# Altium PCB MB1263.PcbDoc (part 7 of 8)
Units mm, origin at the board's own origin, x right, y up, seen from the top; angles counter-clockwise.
Board outline 86 x 120 mm, 6 copper layers (Top Layer, Signal Layer 1, Signal Layer 2, Signal Layer 3, Signal Layer 4, Bottom Layer), stack 1.556 mm thick; 392 components, 421 nets, 1978 pads, 1444 vias.
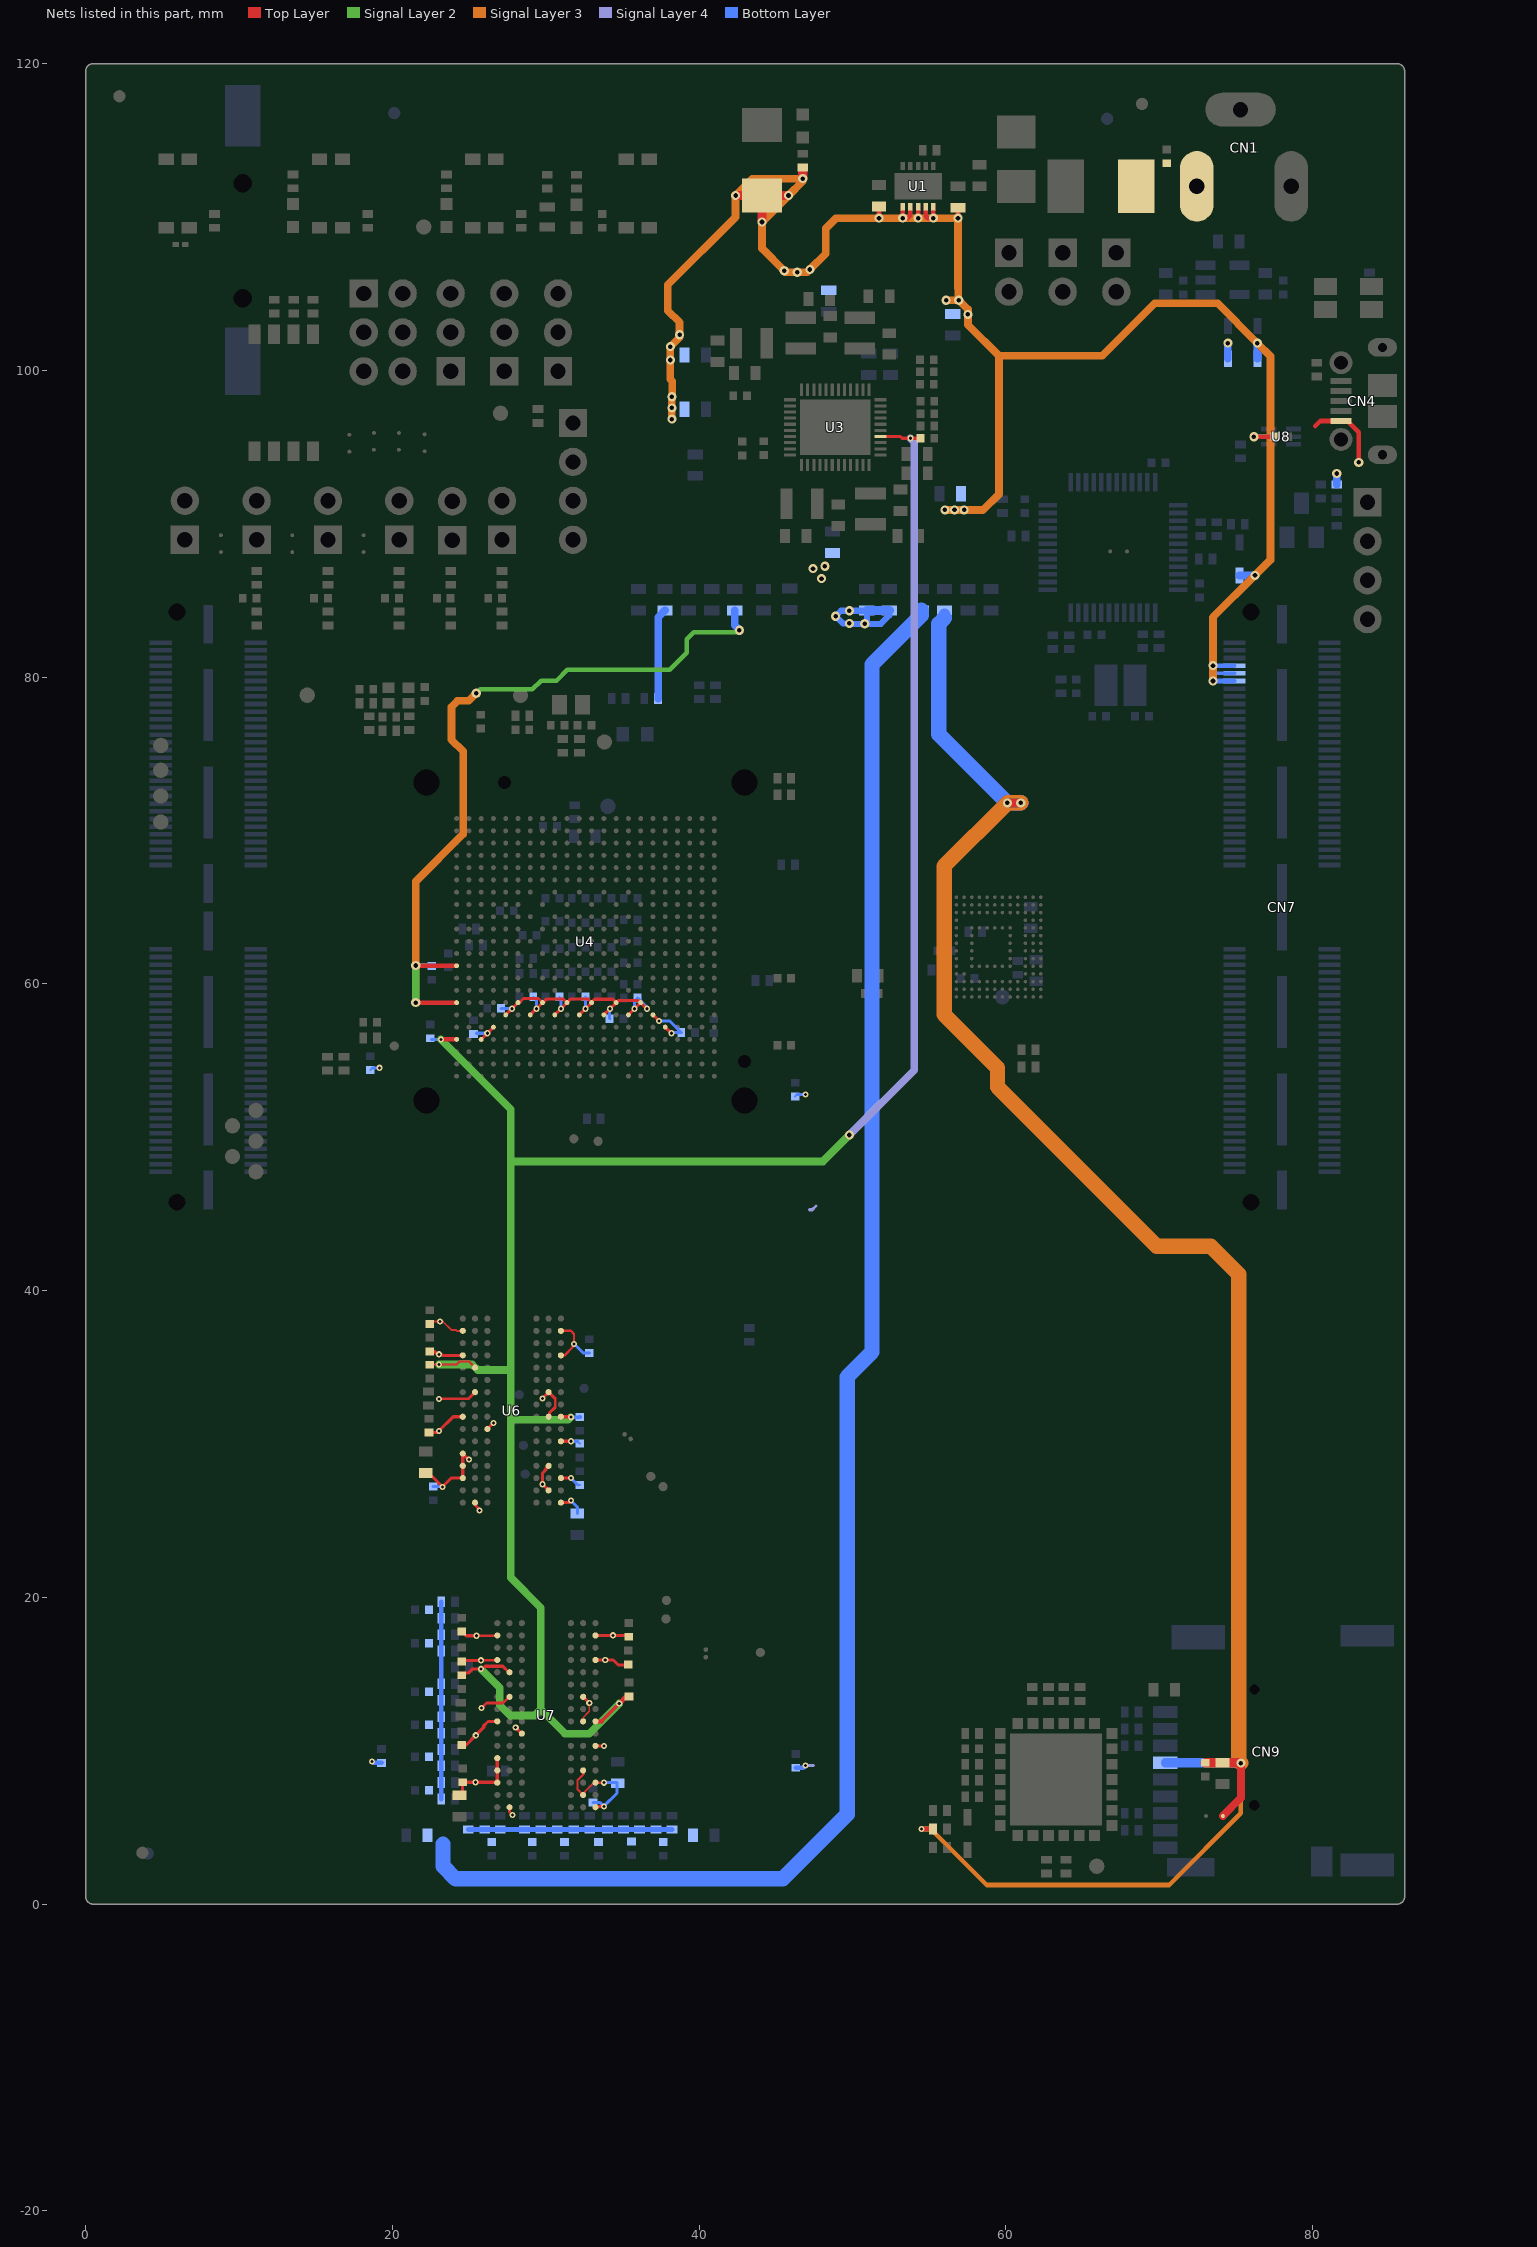
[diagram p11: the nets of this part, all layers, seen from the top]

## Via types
v1: diameter 0.4, hole 0.2, Top Layer to Bottom Layer, tented both sides, 771 vias
v2: diameter 0.6, hole 0.3, Top Layer to Bottom Layer, tented both sides, 670 vias
v3: diameter 0.4, hole 0.2, Top Layer to Bottom Layer, 3 vias

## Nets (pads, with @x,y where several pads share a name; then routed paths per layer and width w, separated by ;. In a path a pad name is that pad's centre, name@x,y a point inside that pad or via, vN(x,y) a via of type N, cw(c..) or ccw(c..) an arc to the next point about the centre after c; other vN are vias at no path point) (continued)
VDD_DDR: C44.1 C45.1 C47.1 C48.2 C49.1 C50.1 C51.1 C52.1 C59.2 C65.1 C66.1 C105.2 C106.2 C107.2 C108.2 C109.2 C110.2 C112.2 C114.2 C115.1 C116.1 C117.1 C119.1 C120.1 C121.1 C122.2 C127.1 C128.1 C130.2 C131.1 LNK2.2 R79.1 R80.2 U4.E18 U4.F17 U4.G16 U4.H17 U4.J16 U4.K17 U4.L16 U4.M17 U4.N16 U4.P17 U4.R16 U4.T17 U4.U16 U4.V17 U4.W18 U4.Y19 U6.A1 U6.A8 U6.B2 U6.C1 U6.C9 U6.D2 U6.D9 U6.E9 U6.F1 U6.G7 U6.H2 U6.H9 U6.K2 U6.K8 U6.N1 U6.N9 U6.R1 U6.R9 U7.A1 U7.A8 U7.B2 U7.C1 U7.C9 U7.D2 U7.D9 U7.E9 U7.F1 U7.G7 U7.H2 U7.H9 U7.K2 U7.K8 U7.N1 U7.N9 U7.R1 U7.R9 | length 100.6
  Top Layer w0.12: C44.1@22.43,37.82 22.6,37.99 v1(23.11,37.99) 23.291,37.99 23.841,37.44 24.139,37.44 24.199,37.38 U6.R9@24.59,37.38 U6.R9@24.64,37.38 ; U6.C1@30.979,27.825 U6.C1@31.004,27.8 ; U7.H2@32.44,11.92 32.44,12.17 32.84,12.57 v1(32.84,13.12) ; U7.A1@33.24,6.32 U7.A1@33.3,6.38 ; U4.G16@36.19,58.73 36.19,58.76 U4.G16@36.19,58.78
  Top Layer w0.15: v1(23.03,32.94) 23.045,32.955 24.965,32.955 ; v1(25.49,17.5) 25.5,17.51 U7.R9@26.8,17.51 ; v1(25.79,15.9) U7.N9@26.79,15.9 ; 30.615,32.405 30.615,32.955 ; U6.N1@30.99,35.78 31.22,35.78 31.76,36.32 31.76,36.45 v1(31.84,36.53) 31.84,37.18 31.64,37.38 U6.R1@30.99,37.38 ; U7.D2@32.44,8.72 32.44,8.45 32.285,8.295 32.065,8.075 32.065,7.495 U7.B2@32.44,7.12 32.44,7.23 33.13,7.92 U7.C1@33.24,7.92 v1(33.79,7.92)
  Top Layer w0.2: C48.2@22.18,28.11 22.37,28.11 v1(23.27,27.21) 23.84,27.78 U6.C9@24.59,27.78 U6.D9@24.59,28.58 U6.E9@24.59,29.38 v1(24.99,28.98) ; C47.1@22.39,30.75 22.93,30.75 v1(23.03,30.85) 23.96,31.78 U6.H9@24.59,31.78 ; C45.1@22.43,36.04 22.73,36.04 22.92,35.85 v1(23.04,35.85) 23.193,35.85 23.263,35.78 U6.N9@24.59,35.78 ; C59.2@24.38,7.1 24.58,7.3 24.58,7.95 v1(25.43,7.95) 26.81,7.95 U7.C9@26.84,7.92 U7.D9@26.84,8.72 U7.E9@26.84,9.52 ; C51.1@24.52,15.83 24.59,15.9 v1(25.79,15.9) ; C65.1@24.53,10.37 24.8,10.37 v1(25.44,11.01) 25.96,11.53 25.96,11.64 26.23,11.91 U7.H9@26.8,11.91 ; C49.1@24.53,17.77 24.8,17.5 v1(25.49,17.5) ; U6.E9@24.64,29.38 U6.E9@24.683,29.38 ; U6.H9@24.64,31.75 U6.H9@24.64,31.78 ; 24.965,32.955 U6.K8@25.39,33.38 U6.K8@25.44,33.38 ; U6.A8@25.39,26.18 25.39,26.02 25.69,25.72 25.68,25.71 v1(25.68,25.67) ; U4.Y19@25.79,56.38 v1(26.19,56.78) U4.W18@26.59,57.18 ; v1(25.8,12.78) 26.14,13.12 27.21,13.12 U7.K8@27.6,13.51 ; U6.G7@26.19,30.98 v1(26.59,31.38) ; U7.N9@26.79,15.9 U7.N9@26.8,15.91 ; U4.V17@27.39,57.98 v1(27.79,58.38) U4.U16@28.19,58.78 28.28,58.78 28.55,59.05 29.525,59.05 U4.R16@29.775,58.8 ; U7.A8@27.64,6.32 27.64,6.01 v1(27.83,5.82) ; v1(28.04,11.52) U7.G7@28.44,11.12 ; U4.T17@28.99,57.98 v1(29.39,58.38) U4.R16@29.79,58.78 29.83,58.78 30.075,59.025 31.125,59.025 U4.N16@31.38,58.77 ; v1(29.79,32.98) U6.K2@30.19,33.38 30.615,32.955 ; U6.B2@30.19,26.98 v1(29.79,27.38) 29.79,28.103 30.01,28.323 30.01,28.4 U6.D2@30.19,28.58 ; U6.D2@30.204,28.6 30.204,28.58 30.204,28.572 U6.D2@30.233,28.6 ; U6.B2@30.228,27 U6.B2@30.233,27 ; U6.H2@30.24,31.78 30.24,32.03 30.615,32.405 ; U4.P17@30.59,57.98 v1(30.99,58.38) U4.N16@31.38,58.77 ; U6.A1@30.99,26.18 31.5,26.18 v1(31.64,26.32) ; U6.C1@30.99,27.78 v1@31.59,27.78 ; U6.F1@30.99,30.18 v1@31.6,30.18 ; U4.N16@31.4,58.75 U4.N16@31.38,58.77 ; U4.M17@32.19,57.98 v1(32.59,58.38) U4.L16@32.99,58.78 32.99,58.815 33.175,59 34.375,59 U4.J16@34.575,58.8 ; U7.K2@32.44,13.52 v1(32.84,13.12) ; U4.L16@32.975,58.825 32.95,58.825 32.75,59.025 31.635,59.025 U4.N16@31.39,58.78 U4.N16@31.38,58.77 ; U7.R1@33.2,17.51 33.24,17.51 v1@34.39,17.51 ; U7.F1@33.24,10.32 v1(33.79,10.32) ; U7.N1@33.24,15.92 v1(33.88,15.92) 34.4,15.92 34.73,15.59 35.35,15.59 C52.1@35.39,15.63 ; U7.A1@33.3,6.38 v1(33.79,6.38) ; U4.K17@33.79,57.98 v1(34.19,58.38) U4.J16@34.59,58.78 34.605,58.78 34.75,58.925 36.025,58.925 U4.G16@36.18,58.77 ; v1(34.39,17.53) 35.3,17.53 C50.1@35.4,17.43 ; U4.H17@35.39,57.98 v1(35.79,58.38) ; v1@35.75,58.375 35.785,58.375 v1(35.79,58.38) ; U4.G16@36.19,58.78 U4.G16@36.18,58.77 ; U4.G16@36.19,58.78 v1(36.59,58.38) ; U4.G16@36.225,58.725 36.19,58.76 U4.G16@36.18,58.77 ; U4.F17@36.99,57.98 v1(37.39,57.58) ; U4.E18@37.79,57.18 v1(38.19,56.78) ; v1(35.79,58.38) U4.G16@36.18,58.77
  Signal Layer 4 w0.2: v1(46.93,9.03) 47.455,9.03 ; 47.2,45.275 47.375,45.275 LNK2.2@47.616,45.516
  Bottom Layer w0.12: C115.1@18.56,54.38 C115.1@18.71,54.53 ; v1@23.16,32.93 v1@23.17,32.94 ; v1@23.25,27.23 v1(23.27,27.21) ; v1@27.765,58.405 v1(27.79,58.38) ; C107.2@29.19,59.155 C107.2@29.39,58.955 ; C106.2@30.89,59.155 C106.2@30.99,59.055 ; C119.1@32.08,30.18 C119.1@32.23,30.03 ; C120.1@32.09,27.33 C120.1@32.23,27.33 ; v1@34.165,58.355 v1(34.19,58.38) ; C110.2@34.19,57.73 C110.2@34.215,57.705 ; C116.1@46.26,52.66 C116.1@46.38,52.78
  Bottom Layer w0.2: C115.1@18.71,54.53 v1(19.15,54.53) ; C121.1@22.66,27.23 v1@23.25,27.23 ; C112.2@25.49,56.78 v1(26.19,56.78) ; C109.2@27.09,58.405 v1@27.765,58.405 ; v1(29.39,58.38) C107.2@29.39,58.955 ; v1(30.99,58.38) C106.2@30.99,59.055 ; v1(31.64,26.32) 32.06,25.9 C122.2@32.06,25.47 ; v1(31.64,27.78) C120.1@32.09,27.33 ; v1(31.64,30.18) C119.1@32.08,30.18 ; v1(31.84,36.53) 32.44,35.93 C117.1@32.84,35.93 ; v1(32.59,58.38) C105.2@32.59,59.155 ; C131.1@33.08,6.62 33.55,6.62 v1(33.79,6.38) 34.65,7.24 34.65,7.88 34.65,7.92 v1(33.79,7.92) ; C110.2@34.165,57.73 v1@34.165,58.355 ; v1(35.79,58.38) 35.79,58.88 C108.2@35.99,59.08 36.59,58.48 v1(36.59,58.38) ; v1(37.39,57.58) 38.09,57.58 C114.2@38.84,56.83 38.24,56.83 v1(38.19,56.78) ; C116.1@46.38,52.78 v1(46.94,52.78)
  Bottom Layer w0.3: v1(18.67,9.31) 18.77,9.21 C127.1@19.29,9.21 ; C128.1@46.31,8.9 46.78,8.9 v1@46.91,9.03
  Bottom Layer w0.4: R79.1@52.4,84.35 52.4,84.025 51.85,83.475 v2(50.8,83.475) ; v2(50.8,83.475) 50.952,83.627 50.952,84.35 50.938,84.337 50.927,84.325 50.925,84.325 v2(49.8,84.325) 49.25,84.325 v2(48.9,83.975) 49.375,83.5 v2(49.8,83.5) 49.825,83.475 v2(50.8,83.475)
  Bottom Layer w0.6: R80.2@50.952,84.35 R79.1@52.4,84.35
VDD_SD: C57.1 C58.2 CN9.4 R46.2 R77.2 SB9.2 | length 133.1
  Top Layer w0.3: v1(54.5,4.9) R46.2@55.25,4.9
  Top Layer w0.5: C58.2@72.975,9.2 C58.2@73,9.225 ; SB9.2@74.15,5.75 75.325,6.925 v2(75.325,9.2) v2@75.3,9.225
  Top Layer w0.6: v2(60.1,71.8) v2(60.975,71.8) ; C58.2@73,9.225 C57.1@74.125,9.225 v2@75.3,9.225
  Signal Layer 2 w0.6: v2(60.1,71.8) v2(60.975,71.8)
  Signal Layer 3 w0.3: v1(54.5,4.9) 55.1,4.9 58.75,1.25 70.65,1.25 75.325,5.925 v2(75.325,9.2)
  Signal Layer 3 w1: v2(60.975,71.8) v2(60.1,71.8) 55.975,67.675 55.975,58 59.45,54.525 59.45,53.275 69.825,42.9 73.35,42.9 75.175,41.075 75.175,9.35 v2(75.325,9.2)
  Signal Layer 4 w0.6: v2(60.1,71.8) v2(60.975,71.8)
  Bottom Layer w0.5: v2(75.325,9.2) 75.35,9.2 75.337,9.212 v2@75.325,9.225
  Bottom Layer w0.6: CN9.4@70.4,9.225 75.3,9.225 v2(75.325,9.2) 74.917,9.2
  Bottom Layer w0.7: 56.002,83.852 R77.2@56.002,84.125
  Bottom Layer w1: 56.002,83.852 55.625,83.475 55.625,76.275 v2(60.1,71.8) v2(60.975,71.8)
VDD_USB: C97.2 R83.2 U4.AB13 U4.AB16 | length 55
  Top Layer w0.3: v2(21.525,58.78) U4.AB16@24.19,58.78 ; v2(21.525,61.2) 21.545,61.18 U4.AB13@24.19,61.18
  Signal Layer 2 w0.3: v2@25.425,79 v2(25.475,78.95) 25.725,79.2 29.122,79.2 29.697,79.775 30.7,79.775 31.4,80.475 38.075,80.475 39.2,81.6 39.2,82.475 39.65,82.925 42.5,82.925 v2(42.625,83.05)
  Signal Layer 2 w0.5: v2(21.525,58.78) v2(21.525,61.2)
  Signal Layer 3 w0.5: v2(21.525,58.78) v2(21.525,61.2) 21.525,66.675 24.625,69.775 24.625,75.156 23.85,75.931 23.85,78.05 24.25,78.45 24.975,78.45 v2(25.475,78.95)
  Bottom Layer w0.3: v2(21.525,58.78) v2(21.525,61.2) 21.55,61.175 C97.2@22.575,61.175 ; v2(42.625,83.05) v2@42.65,83.05
  Bottom Layer w0.5: R83.2@42.327,84.35 42.327,83.373 42.637,83.063 v2@42.65,83.05
VDDA: R86.2 R94.1 | length 5.9
  Bottom Layer w0.5: R94.1@37.325,78.6 37.325,83.898 R86.2@37.777,84.35
VIN: C1.1 C4.2 CN7.7 CN7.9 CN7.11 D3.1 D5.1 R2.2 R7.2 R50.1 R59.1 R60.1 R63.1 R68.1 R72.1 U1.1 U1.2 U1.3 U1.4 U1.5 | length 129.5
  Top Layer w0.3: v2(51.725,109.925) C4.2@51.725,110.675 ; U1.1@53.275,110.675 v2(53.275,109.925) 53.6,109.925 53.775,110.1 U1.2@53.775,110.675 ; v2(54.275,109.925) U1.3@54.275,110.675 ; U1.4@54.775,110.675 54.775,110.05 54.9,109.925 v2(55.275,109.925) U1.5@55.275,110.675 ; v2(56.875,109.925) R7.2@56.875,110.6
  Top Layer w0.56: v2(42.375,111.4) C1.1@44.1,111.4 ; v2(44.1,109.675) C1.1@44.1,111.4 ; v2(45.825,111.4) C1.1@44.1,111.4
  Top Layer w0.6: v2(46.75,112.5) R2.2@46.75,113.025
  Signal Layer 3 w0.5: v2@38.1,101.525 v2(38.125,101.55) ; v2@38.2,98.275 38.25,98.325 38.25,99.294 38.125,99.419 v2(38.125,100.675) v2(38.125,101.55) ; v2(38.225,96.825) v2(38.225,97.55) v2(38.225,98.275) ; v2(38.725,102.325) 38.725,102.15 v2(38.125,101.55) ; v2@38.725,102.35 38.725,103.125 37.95,103.9 37.95,105.575 42.375,110 v2(42.375,111.4) 43.475,112.5 v2(46.75,112.5) 46.75,112.325 v2(45.825,111.4) v2(44.1,109.675) 44.1,107.95 v2(45.55,106.5) 45.65,106.4 v2(46.4,106.4) 47.05,106.4 v2(47.225,106.575) 48.25,107.6 48.25,109.25 48.925,109.925 v2(51.725,109.925) v2(53.275,109.925) v2(54.275,109.925) v2(55.275,109.925) v2(56.875,109.925) 56.875,105.35 56.9,105.325 v2@56.9,104.575 ; v2(56.025,90.9) v2(56.65,90.9) v2(57.275,90.9) 58.475,90.9 58.5,90.875 59.55,91.925 59.55,100.95 ; v2@56.1,104.6 56.125,104.575 v2@56.9,104.575 ; v2(73.5,79.75) v2(73.5,80.75) 73.5,83.89 v2(76.24,86.63) 77.25,87.64 77.25,100.925 v2(76.4,101.775) 73.8,104.375 69.7,104.375 66.275,100.95 59.55,100.95 ; v2@56.9,104.575 v2(56.925,104.575) 57.525,103.975 v2(57.525,103.65) 57.525,102.975 59.55,100.95
  Bottom Layer w0.25: v2(73.5,79.75) 73.5,80.25 ; v2(73.5,80.75) 73.5,80.25 ; CN7.9@74.9,80.25 73.5,80.25
  Bottom Layer w0.3: v2(73.5,79.75) CN7.11@74.9,79.75 ; v2(73.5,80.75) CN7.7@74.9,80.75
  Bottom Layer w0.5: D5.1@75.225,86.63 v2(76.24,86.63) ; D3.1@76.4,100.76 v2(76.4,101.775)
  other v2: 47.975,86.425 47.425,87.075 48.2,87.225 56.1,104.575
VIN_JACK: C2.2 CN1.1 F1.1
VREF_DDR: C19.2 C46.1 C53.1 C54.1 C113.2 C118.1 U3.16 U4.AB19 U6.H1 U6.M8 U7.H1 U7.M8 | length 153.1
  Top Layer w0.1: C19.2@54.399,95.684 C19.2@54.427,95.656
  Top Layer w0.15: C46.1@22.44,35.17 22.45,35.18 v1(23.04,35.18) v1@23.19,35.18 ; 23.24,35.18 24.178,35.18 24.378,35.38 24.99,35.38 U6.M8@25.39,34.98 ; U3.16@51.831,95.684 U3.16@51.829,95.686 U3.16@51.854,95.711 ; C19.2@54.339,95.625 54.357,95.643 C19.2@54.399,95.684
  Top Layer w0.2: C53.1@24.52,15.06 24.94,15.06 25.204,15.324 v1(25.79,15.324) 25.854,15.324 26.04,15.51 27.2,15.51 27.6,15.11 27.6,15.12 U7.M8@27.6,15.16 ; U3.16@51.829,95.686 53.114,95.686 53.225,95.575 v1(53.775,95.575) 54.289,95.575 C19.2@54.339,95.625
  Top Layer w0.25: U6.H1@30.99,31.78 31.61,31.78 v1(31.64,31.75) ; U7.H1@33.24,11.92 33.67,11.92 33.67,11.96 v1(34.79,13.08) ; C54.1@35.26,13.55 C54.1@35.43,13.55
  Top Layer w0.3: v1(23.165,56.38) U4.AB19@24.19,56.38 ; v1(34.79,13.08) C54.1@35.26,13.55
  Signal Layer 2 w0.5: v1(23.04,35.18) 25.212,35.18 25.562,34.83 27.616,34.83 27.719,34.933 ; v1(23.165,56.38) 27.719,51.826 27.719,48.425 ; v1(25.79,15.324) 27,14.114 27,12.975 27.675,12.3 29.29,12.3 29.685,12.695 ; v1(31.64,31.75) 31.47,31.58 27.819,31.58 27.719,31.48 ; v1(34.79,13.08) 32.83,11.12 31.26,11.12 29.685,12.695 ; v2(49.8,50.15) 48.075,48.425 27.719,48.425 ; 27.719,31.48 27.719,21.3 29.685,19.334 29.685,12.695 ; 27.719,31.48 27.719,34.933 ; 27.719,34.933 27.719,48.425
  Signal Layer 4 w0.3: v1(53.775,95.575) v1@53.836,95.575
  Signal Layer 4 w0.5: v2(49.8,50.15) 54.025,54.375 54.025,95.325 v1(53.775,95.575)
  Bottom Layer w0.2: C113.2@22.54,56.38 v1(23.165,56.38)
  Bottom Layer w0.25: v1(31.64,31.75) 32.21,31.75 C118.1@32.23,31.77
VTT_DDR: C123.1 C124.1 C125.1 C126.1 C129.1 C132.1 C133.2 C134.2 C135.1 C136.1 C137.1 C138.1 C139.1 C140.1 R78.2 R104.2 R105.2 R106.2 R107.2 R109.2 R110.2 R112.2 R114.2 R116.2 R117.2 R119.2 R120.2 R122.2 R123.2 R124.2 R125.2 R126.2 R127.2 R128.2 R129.2 R130.2 R131.2 R132.2 R133.2 R134.2 | length 136.5
  Bottom Layer w0.3: R120.2@23.19,6.85 R119.2@23.19,7.94 R117.2@23.19,9.02 R116.2@23.19,10.09 R114.2@23.19,11.15 R112.2@23.19,12.22 R110.2@23.19,13.29 R109.2@23.19,14.37 R107.2@23.19,16.5 R106.2@23.19,17.57 R105.2@23.19,18.64 R104.2@23.19,19.72 ; R134.2@24.94,4.87 R133.2@26.02,4.87 R132.2@27.04,4.87 R131.2@28.62,4.87 R130.2@29.68,4.87 R129.2@30.75,4.87 R128.2@31.82,4.87 R127.2@32.87,4.87 R126.2@34.03,4.87 R125.2@35.07,4.87 R124.2@36.12,4.87 R123.2@37.19,4.87 R122.2@38.23,4.87
  Bottom Layer w1: 23.3,3.925 23.3,2.475 24.125,1.65 45.45,1.65 49.65,5.85 49.65,34.375 51.275,36 51.275,80.825 54.477,84.027 R78.2@54.477,84.35
VUSB_ST_LINK: C18.2 CN4.1 D4.1 R52.2 U8.5 | length 9.3
  Top Layer w0.3: v2(76.17,95.675) C18.2@77.495,95.675 ; 80.175,96.375 80.5,96.7 CN4.1@81.85,96.7 81.875,96.675 82.3,96.675 83,95.975 v2(83,94)
  Bottom Layer w0.3: v2(76.17,95.675) U8.5@77.14,95.675
  Bottom Layer w0.5: D4.1@74.475,100.76 v2(74.475,101.775) ; R52.2@81.575,92.55 v2(81.575,93.275)
pads on no net: BT1.NPTH1 BT1.NPTH2 CN7.1 CN7.3 CN7.5 CN7.6 CN7.12 CN7.13 CN7.18 CN7.19 CN7.21 CN7.22 CN7.23 CN7.25 CN7.92 CN7.94 CN7.119 CN7.FIX1 CN7.FIX2 CN8.14 CN8.16 CN8.18 CN8.35 CN8.55 CN8.67 CN8.73 CN8.83 CN8.85 CN8.102 CN8.106 CN8.110 CN8.114 CN8.117 CN8.118 CN8.119 CN8.FIX1 CN8.FIX2 CN9.11 CN9.12 CN9.13 CN9.14 CN9.NPTH1 CN9.NPTH2 M1.26 M1.27 MIRE1.1 MIRE2.1 MIRE3.1 MIRE4.1 MIRE5.1 MIRE6.1 SW1.5 U1.8 U1.9 U4.C4 U4.D1 U4.D7 U4.NPTH1 U4.NPTH2 U4.NPTH3 U4.NPTH4 U4.NPTH5 U4.NPTH6 U5.A1 U5.A2 U5.A7 U5.A8 U5.A9 U5.A10 U5.A11 U5.A12 U5.A13 U5.A14 U5.B1 U5.B7 U5.B8 U5.B9 U5.B10 U5.B11 U5.B12 U5.B13 U5.B14 U5.C1 U5.C3 U5.C5 U5.C7 U5.C8 U5.C9 U5.C10 U5.C11 U5.C12 U5.C13 U5.C14 U5.D1 U5.D2 U5.D3 U5.D4 U5.D12 U5.D13 U5.D14 U5.E1 U5.E2 U5.E3 U5.E5 U5.E8 U5.E9 U5.E10 U5.E12 U5.E13 U5.E14 U5.F1 U5.F2 U5.F3 U5.F10 U5.F12 U5.F13 U5.F14 U5.G1 U5.G2 U5.G3 U5.G10 U5.G12 U5.G13 U5.G14 U5.H1 U5.H2 U5.H3 U5.H12 U5.H13 U5.H14 U5.J1 U5.J2 U5.J3 U5.J12 U5.J13 U5.J14 U5.K1 U5.K2 U5.K3 U5.K6 U5.K7 U5.K10 U5.K12 U5.K13 U5.K14 U5.L1 U5.L2 U5.L3 U5.L12 U5.L13 U5.L14 U5.M1 U5.M2 U5.M3 U5.M7 U5.M8 U5.M9 U5.M10 U5.M11 U5.M12 U5.M13 U5.M14 U5.N1 U5.N3 U5.N6 U5.N7 U5.N8 U5.N9 U5.N10 U5.N11 U5.N12 U5.N13 U5.N14 U5.P1 U5.P2 U5.P7 U5.P8 U5.P9 U5.P10 U5.P11 U5.P12 U5.P13 U5.P14 U6.J1 U6.J9 U6.L1 U6.L9 U7.J1 U7.J9 U7.L1 U7.L9 U10.4 U10.11 U10.14 U10.22 U10.28 U10.29 U10.40 U10.41 U10.42 U10.43 U10.45 U10.46
copper on no net:
  other v1: 4.75,84.925 2,87.175
  other v2: 5,108.2

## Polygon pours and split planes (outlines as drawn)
GND on Bottom Layer "GND" (solid, remove dead copper, pour order 324): 0,119.75 0,0.25 0.25,0 21.25,0 21.25,21.75 20.347,22.653 20.347,37.403 17.675,40.075 17.675,52.925 25,60.25 25,67.92 26.08,69 39.325,69 40.25,68.075 40.25,61.25 48.95,52.55 48.95,38.95 45.75,35.75 37.75,35.75 36.5,34.5 36.5,19 42.25,13.25 42.25,0 85.75,0 86,0.25 86,119.75
NetC9_2 on Bottom Layer "NO FT" (solid, remove dead copper, pour order 314): 47.8,104.325 48.975,104.325 49.25,104.05 49.25,102.725 48.95,102.425 47.775,102.425 47.55,102.65 47.55,104.075
NetC9_2 on Bottom Layer "NO FT" (solid, remove dead copper, pour order 232): 49.125,107.15 49,107.025 49,103.375 49.2,103.175 49.875,103.175 50.1,103.4 50.1,107 49.95,107.15
3V3 on Bottom Layer "3V3_L06_P140" (solid, remove dead copper, pour order 140): 4.1,82.2 4.1,80.625 4.225,80.5 6.225,80.5 6.475,80.75 6.475,83.15 5.2,84.425 3,84.425 3,83.3
VTT_DDR on Bottom Layer "VTT_DDR" (solid, remove dead copper, pour order 26): 36.911,5.4 40.3,5.4 40.3,3.51 21.82,3.51 21.82,20.48 23.75,20.48 23.75,5.4 35.875,5.4 36.49,5.4
NetC14_2 on Bottom Layer "NO FT" (solid, remove dead copper, pour order 248): 40.025,98.325 39.95,98.25 39.95,96.9 40.125,96.725 42.05,96.725 42.475,97.15 42.475,98.075 42.225,98.325
BST_OUT on Bottom Layer "BST_OUT_L06_P166" (solid, remove dead copper, pour order 166): 42.452,97.231 42.452,96.856 42.627,96.681 44.281,96.681 46.2,98.6 46.2,99.408 45.127,100.481 44.356,100.481 42.452,98.577
NetC6_2 on Bottom Layer "NO FT" (solid, remove dead copper, pour order 322): 43.4,88.55 43.6,88.75 44.7,88.75 44.925,88.525 44.925,85.5 44.675,85.25 43.55,85.25 43.4,85.4
NetC27_2 on Bottom Layer "NO FT" (solid, remove dead copper, pour order 152): 46.575,85.475 46.375,85.275 45.35,85.275 45.025,85.6 45.025,88.6 45.175,88.75 46.425,88.75 46.575,88.6
VIN on Bottom Layer "NO FT" (solid, remove dead copper, pour order 304): 49.375,88.45 49.375,86.9 48.4,85.925 47.425,85.925 46.9,86.45 46.9,87.325 48.2,88.625 49.2,88.625
VDD_CORE on Bottom Layer "NO FT" (solid, remove dead copper, pour order 296): 45.266,85.075 45.266,82.984 45.575,82.675 47.45,82.675 47.9,83.125 47.9,84 46.825,85.075
VIN on Bottom Layer "NO FT" (solid, remove dead copper, pour order 234): 56.025,105.075 55.75,104.8 55.75,103.3 55.95,103.1 57.45,103.1 57.85,103.5 57.85,104.825 57.6,105.075
VIN on Bottom Layer "NO FT" (solid, remove dead copper, pour order 242): 38.075,98.675 37.875,98.475 37.875,96.625 38.025,96.475 38.7,96.475 38.925,96.7 39.425,96.7 39.575,96.85 39.575,98.375 39.275,98.675
NetC10_2 on Bottom Layer "NO FT" (solid, remove dead copper, pour order 240): 54.325,102.75 54.025,102.45 54.025,101.275 54.25,101.05 56.95,101.05 57.225,101.325 57.225,102.6 57.075,102.75
VIN on Bottom Layer "NO FT" (solid, remove dead copper, pour order 230): 47.95,107.15 49.125,105.975 49.125,104.875 48.85,104.6 47.975,104.6 46.7,105.875 45.412,105.913 45.175,106.15 45.175,106.925 45.4,107.15
NetC7_2 on Bottom Layer "NO FT" (solid, remove dead copper, pour order 164): 36.7,85.375 37.002,85.677 37.002,86.281 37.277,86.556 37.277,88.181 36.927,88.531 35.152,88.531 34.902,88.281 34.902,85.973 35.5,85.375
VDD_DDR on Bottom Layer "NO FT" (solid, remove dead copper, pour order 268): 52.9,84.778 53.008,84.67 53.008,83.983 51.825,82.8 49.275,82.8 48.575,83.5 48.575,84.275 49.078,84.778
3V3 on Bottom Layer "NO FT" (solid, remove dead copper, pour order 270): 36.55,85.2 36.702,85.048 36.702,83.927 36.525,83.75 33.1,83.75 32.775,84.075 32.775,84.925 33.325,85.475 35.075,85.475 35.35,85.2
NetC25_2 on Bottom Layer "NO FT" (solid, remove dead copper, pour order 302): 49.975,90.925 49.975,89.75 49.25,89.025 48.075,89.025 47.95,89.15 47.95,90.6 48.45,91.1 49.8,91.1
NetC26_2 on Bottom Layer "NO FT" (solid, remove dead copper, pour order 306): 52.25,89.3 52.25,87.825 51.675,87.25 51.675,85.4 51.475,85.2 50.4,85.2 50.1,85.5 50.1,89.325 50.375,89.6 51.95,89.6
NetC24_2 on Bottom Layer "NO FT" (solid, remove dead copper, pour order 308): 54.375,92.775 55.775,92.775 56.125,92.425 56.125,91.45 56,91.325 55.65,91.325 55.375,91.05 55.375,90.7 55.2,90.525 54.325,90.525 54.125,90.725 54.125,92.525
NetC8_2 on Bottom Layer "NO FT" (solid, remove dead copper, pour order 316): 40.05,103.25 41.55,103.25 41.8,103 41.8,102.4 41.125,101.725 41.125,100.475 40.95,100.3 40.025,100.3 39.825,100.5 39.825,101.925 39.825,103.025
VIN on Bottom Layer "NO FT" (solid, remove dead copper, pour order 318): 39.65,102.994 39.65,100.5 39.45,100.3 37.775,100.3 37.65,100.425 37.65,103 37.9,103.25 39.357,103.25
VIN on Bottom Layer "NO FT" (solid, remove dead copper, pour order 310): 56.45,91.5 56.2,91.25 55.775,91.25 55.575,91.05 55.575,90.525 55.75,90.35 57.275,90.35 57.625,90.7 57.625,92.475 57.45,92.65 56.55,92.65 56.45,92.55
GND on Top Layer "GND" (solid, remove dead copper, pour order 328): 11.75,25.75 14.5,23 18.5,23 21.25,20.25 21.25,4.5 22.75,3 36.73,3 43.75,10.02 43.75,67.8 39.3,72.25 0,72.25 0,120 85.75,120 86,119.75 86,0.25 85.75,0 0.25,0 0,0.25 0,72.25 22.25,72.25 22.25,57.925 11.75,47.425
NetC22_2 on Top Layer "NO FT" (solid, remove dead copper, pour order 286): 52.175,94.8 52.95,94.025 53.8,94.025 53.975,94.2 53.975,94.9 53.8,95.075 52.9,95.075 52.85,95.125 51.6,95.125 51.45,94.975 51.45,94.8
NetC23_2 on Top Layer "NO FT" (solid, remove dead copper, pour order 284): 51.425,94.375 53,92.8 53.85,92.8 53.95,92.9 53.95,93.7 53.775,93.875 53.075,93.875 52.775,94.175 52.625,94.175 52.225,94.575 51.425,94.575
VUSB_ST_LINK on Top Layer "VUSB_ST_LINK_L01_P250" (solid, remove dead copper, pour order 250): 72.575,103.8 72.075,103.3 72.075,100.825 71.475,100.225 62.125,100.225 61.45,99.55 61.45,96.725 63.1,95.075 75.475,95.075 77.825,92.725 82.925,92.725 83.55,93.35 83.55,96.15 82.85,96.85 79.025,96.85 75.85,100.025 75.85,103.35 75.4,103.8
GND on Top Layer "GND_L01_P228" (solid, remove dead copper, pour order 228): 42.1,118.4 41.625,117.925 41.625,114.525 42.275,113.875 45.5,113.875 45.9,114.275 45.9,115.75 46.125,115.975 47.375,115.975 47.625,116.225 47.625,116.825 47.9,117.1 50.1,117.1 50.4,116.8 50.4,114.725 51.025,114.1 51.025,111.825 51.225,111.625 52.275,111.625 52.425,111.775 52.425,112.85 52.625,113.05 53.475,113.05 53.55,113.125 53.55,113.675 53.925,114.05 53.925,114.9 54.175,115.15 55.85,115.15 56.125,114.875 56.125,113.425 56.5,113.05 58.8,113.05 59.7,113.95 61.875,113.95 62.25,114.325 71.3,114.325 71.75,114.775 74.175,114.775 75.025,113.925 75.025,109.975 75.575,109.425 80.575,109.425 81.25,110.1 81.25,117.875 80.725,118.4
VIN on Top Layer "VIN_L01_P212" (solid, remove dead copper, pour order 212): 50.175,114.375 50.675,113.875 50.675,112.275 50.4,112 48.2,112 47.475,111.275 47.475,109.725 47.025,109.275 41.925,109.275 41.625,109.575 41.625,112.85 42.4,113.625 47.375,113.625 48.125,114.375
NetC3_2 on Top Layer "NETC3_2_L01_P210" (solid, remove dead copper, pour order 210): 65.225,114 62.375,114 62.05,113.675 59.8,113.675 59,112.875 52.75,112.875 52.75,111.125 52.775,111.15 55.95,111.15 56.1,111.3 57.825,111.3 59.675,109.45 65.175,109.45 65.75,110.025 65.75,113.475
VIN_JACK on Top Layer "VIN_JACK_L01_P206" (solid, remove dead copper, pour order 206): 73.925,114.425 74.525,113.825 74.525,110.15 73.85,109.475 67.1,109.475 66.6,109.975 66.6,113.725 66.875,114 71.4,114 71.825,114.425
NetC24_2 on Top Layer "NO FT" (solid, remove dead copper, pour order 204): 52.427,92.373 52.427,91.998 52.675,91.75 53.92,91.75 54.15,91.52 54.15,90.85 54.475,90.525 55,90.525 55.275,90.8 55.275,92.35 54.869,92.756 54.675,92.756 53.069,92.756 51.869,93.956 51.577,93.956 51.227,94.306 50.979,94.306 50.979,93.404 51.808,92.575 52.225,92.575
NetL5_1 on Top Layer "NO FT" (solid, remove dead copper, pour order 198): 48.2,91.554 48.2,90.2 48.1,90.1 47.2,90.1 46.9,90.4 46.9,92.2 47.2,92.5 48.147,92.5 49.003,93.356 49.044,93.356 49.175,93.225 49.175,92.529
NetC25_2 on Top Layer "NO FT" (solid, remove dead copper, pour order 196): 49.3,93.375 49.375,93.45 49.575,93.45 49.65,93.375 49.65,92.525 49.725,92.45 49.725,90.275 49.55,90.1 49.55,90.05 48.725,90.05 48.45,90.325 48.45,91.677 48.712,91.939 49.023,92.252 49.3,92.529
NetC10_2 on Top Layer "NO FT" (solid, remove dead copper, pour order 194): 51.675,101.325 51.825,101.475 52.475,101.475 53.037,102.037 53.65,102.037 56.488,102.037 56.775,101.75 56.775,101.35 56.525,101.1 54.775,101.075 53.275,101.075 51.55,99.35 51,99.35 50.8,99.125 50.575,99.125 50.575,99.575 51.675,100.675
NetC14_2 on Top Layer "NO FT" (solid, remove dead copper, pour order 188): 46.277,97.481 42.602,97.481 42.096,96.975 41,96.975 40.725,97.25 40.725,97.925 41.506,98.706 44.502,98.706 45.352,97.856 46.227,97.856 46.277,97.806
NetL3_2 on Top Layer "NO FT" (solid, remove dead copper, pour order 176): 44,102.95 43.825,102.775 43.825,100.725 43.975,100.576 45.025,100.575 46.344,99.256 46.894,99.256 46.95,99.2 46.95,99.1 46.975,99.075 47.175,99.075 47.2,99.1 47.2,99.558 45.3,101.453 45.3,102.525 44.875,102.95
NetC67_2 on Top Layer "NO FT" (solid, remove dead copper, pour order 292): 52.075,98 53.625,99.55 54.075,99.55 54.15,99.625 54.15,100.175 54.05,100.275 53.475,100.275 51.425,98.225 51.425,98
BST_OUT on Top Layer "NO FT" (solid, remove dead copper, pour order 190): 43.252,100.431 43.127,100.306 43.127,99.606 43.377,99.356 44.877,99.356 45.902,98.331 46.727,98.331 46.777,98.381 46.777,99.106 46.752,99.131 46.327,99.131 45.027,100.431
NetC8_2 on Top Layer "NO FT" (solid, remove dead copper, pour order 180): 42,100.575 41.85,100.725 41.85,101.225 41.65,101.425 40.047,101.425 39.8,101.678 39.8,102.874 40.06,103.135 42.834,103.135 42.982,102.988 42.982,100.682 42.875,100.575
NetL2_1 on Top Layer "NO FT" (solid, remove dead copper, pour order 192): 50.375,99.025 50.425,99.075 50.425,99.625 51.575,100.775 51.575,101.825 51.425,101.975 49.475,101.975 49.275,101.775 49.275,100.875 50.175,99.975 50.175,99.025
NetL4_1 on Top Layer "NO FT" (solid, remove dead copper, pour order 202): 50.05,91.55 50.15,91.45 52.2,91.45 52.3,91.55 52.3,92.35 52.175,92.475 51.75,92.475 50.775,93.45 50.577,93.45 50.577,93.175 50.577,92.927 50.05,92.4
NetC7_2 on Top Layer "NO FT" (solid, remove dead copper, pour order 182): 51.75,104.1 51.75,105.675 52.2,106.125 53.975,106.125 54.152,106.325 54.152,106.631 53.927,106.856 50.827,106.856 50.55,106.575 50.55,104.225 50.4,104.075 49.55,104.075 49.25,103.775 49.25,103.025 49.425,102.85 51.4,102.85 51.575,103.025 51.575,103.925
NetC27_2 on Top Layer "NO FT" (solid, remove dead copper, pour order 186): 45.277,87.625 45.452,87.45 46.375,87.45 46.575,87.65 46.575,92.019 46.194,92.4 45.275,92.4 45.025,92.15 45.025,88.133 45.277,87.881
NetC26_2 on Top Layer "NO FT" (solid, remove dead copper, pour order 300): 52.1,90.5 52.15,90.5 52.325,90.325 52.325,89.95 52.45,89.825 53.225,89.825 53.425,89.625 53.425,88.75 53.275,88.6 50.525,88.6 50.025,89.1 50.025,90.325 50.2,90.5
NetL1_1 on Top Layer "NO FT" (solid, remove dead copper, pour order 172): 48.108,100.825 45.75,100.825 45.45,101.125 45.45,101.725 45.675,101.95 47.805,101.95 48.758,101.025 48.777,101.006 48.777,100.404 48.679,100.306 48.627,100.306
NetC9_2 on Top Layer "NO FT" (solid, remove dead copper, pour order 312): 49.175,100.6 49.175,102.825 48.975,103.025 47.875,103.025 47.75,102.9 47.75,102.075 48.975,100.85 48.975,100.6
NetC6_2 on Top Layer "NO FT" (solid, remove dead copper, pour order 320): 47.487,105.988 47.85,105.625 47.85,103.125 47.525,102.8 45.6,102.8 45.325,103.075 45.325,104.5 45.025,104.8 38.625,104.8 38.375,105.05 38.375,105.725 38.613,105.963
GND on Signal Layer 2 "GND_L03_P272" (solid, remove dead copper, pour order 272): 0,120 0,0 86,0 86,120
3V3_ST_LINK on Signal Layer 2 "3V3_ST_LINK_L03_P252" (solid, remove dead copper, pour order 252): 61.05,78.35 62.025,77.375 65.65,77.375 66.7,78.425 66.7,80.625 68.375,82.3 84.075,82.3 84.75,82.975 84.75,92.225 83.375,93.6 83.375,101.975 84.6,103.2 84.6,107.65 84.2,108.05 84.125,107.975 77.975,107.975 76.85,106.85 76.85,99.5 74.15,96.8 61.775,96.8 60.1,95.125 60.1,81.25 61.05,80.3
VDD on Signal Layer 2 "VDD_L03_P114" (solid, remove dead copper, pour order 114): 39.9,82.7 39.325,82.125 39.325,81.475 38.3,80.45 31.77,80.45 31.225,79.996 31.225,73.5 32.8,71.925 51.5,71.925 51.525,71.9 83.25,71.9 84.3,72.95 84.3,81 83.575,81.725 68.804,81.71 67.25,80.156 67.25,78.2 65.95,76.9 61.85,76.9 60.55,78.2 60.55,80 55.74,84.81 43.447,84.797 41.35,82.7
VDD on Signal Layer 2 "VDD_L03_P108" (solid, remove dead copper, pour order 108): 37.787,58.262 37.787,56.863 38.25,56.4 41.175,56.4 41.75,55.825 41.75,52.725 41.825,52.65 46.9,52.65 49.25,50.3 49.25,4.125 52.3,1.075 66.3,1.075 68.525,3.3 68.525,55.725 61.425,62.825 42.2,62.825 40.6,61.225 38.175,61.225 37.525,61.875 35.895,61.875 35.245,62.525 33.85,62.525 33.55,62.825 33.55,64.925 33.125,65.35 30.475,65.35 30.05,65.775 29.125,65.775 28.075,64.725 28.075,60.3 28.05,60.275 28.075,60.25 28.075,59.775 28.725,59.125 28.8,59.1 35.2,59.1 35.55,58.75 36.05,58.75 36.15,58.65 36.15,58.625 37.425,58.625
2V8 on Signal Layer 2 "2V8_L03_P266" (solid, remove dead copper, pour order 266): 8.425,81.925 9.125,81.225 9.925,81.225 10.475,81.775 10.475,82.4 12.575,84.5 27.8,84.5 28.825,85.525 41.05,85.525 41.55,85.025 56.875,85.025 58.025,83.875 58.025,82.825 58.325,82.525 59.55,82.525 59.85,82.825 59.85,86.95 58.875,87.925 12.525,87.925 8.425,83.825
VBUS_SW on Signal Layer 2 "VBUS_SW_L03_P262" (solid, remove dead copper, pour order 262): 3.225,78 3.725,78 4.025,77.7 4.025,76.275 3.75,76 1.525,76 1.1,76.425 1.1,81.45 1.475,81.825 8.225,81.825 9,81.05 10.325,81.05 10.8,81.525 10.8,82.275 12.85,84.325 28.1,84.325 29.025,85.25 40.9,85.25 41.725,84.425 41.725,83.325 41.375,82.975 39.65,82.975 39.4,83.225 39.4,83.725 39.075,84.05 37.8,84.05 36.25,82.5 30.45,82.5 29.24,81.29 13.04,81.29 11.425,79.675 4.775,79.675 4.15,80.3 2.775,80.3 2.525,80.05 2.525,78.7
VBUS_OTG on Signal Layer 2 "VBUS_OTG_L03_P260" (solid, remove dead copper, pour order 260): 38.775,83.9 39.075,83.6 39.075,81.725 38.075,80.725 31.65,80.725 30.65,79.725 22.5,79.725 20.975,78.2 3.6,78.2 2.85,78.95 2.85,79.925 3,80.075 3.975,80.075 4.675,79.375 11.525,79.375 13.1,80.95 29.5,80.95 30.71,82.16 36.285,82.16 38.025,83.9
3V3 on Signal Layer 4 "3V3_L05_P256" (solid, remove dead copper, pour order 256): 57.052,103 58.55,101.593 58.55,88.475 54.875,84.8 54.875,63.75 55.325,63.3 57.517,63.3 57.775,63.042 57.775,60.525 58.85,59.45 61.6,59.45 63.275,61.125 83.6,61.125 84.725,62.25 84.725,92.75 83.825,93.65 83.825,102.25 84.575,103 84.575,117.825 83.825,118.575 2.05,118.575 1.125,117.65 1.125,82.725 1.575,82.275 9.65,82.275 10.1,82.725 10.1,106.425 11.5,107.825 26.725,107.825 29.3,105.25 29.3,86.3 31.775,83.825 34.675,83.825 35.252,84.402 35.252,85.598 34.25,86.6 34.25,105.425 37.3,108.475 54.325,108.475 54.85,107.95 54.85,106.2 54,105.35 54,103.325 54.325,103
GND on Signal Layer 4 "GND_L05_P144" (solid, remove dead copper, pour order 144): 48.25,48.5 48.25,3 47.75,2.5 18,2.5 17.75,2.75 17.75,51.137 17.137,51.75 10.75,51.75 10,52.5 10,81.475 9.475,82 0,82 0,0.25 0.25,0 86,0 86,54.7 86.025,54.725 86.025,61.875 85.225,61.875 83.95,60.6 66.125,60.6 65.625,60.1 65.625,55.125 64.25,53.75 53.5,53.75
VDD on Signal Layer 4 "VDD_L05_P106" (solid, remove dead copper, pour order 106): 31.339,62.198 29.633,60.492 28.117,60.492 26.967,59.342 18.283,59.342 17.808,58.867 17.808,52.992 17.208,52.392 11.508,52.392 10.608,53.292 10.608,106.167 11.808,107.367 26.558,107.367 28.908,105.017 28.908,86.217 31.633,83.492 35.033,83.492 37.233,85.692 41.733,85.692 44.758,85.692 44.758,85.642 45.058,85.323 45.058,82.217 44.633,81.792 39.783,81.792 36.358,78.367 33.033,78.367 32.383,77.717 32.383,64.017 32.158,63.792 31.633,63.792 31.358,63.517 31.358,62.467 31.333,62.442
VDD_CORE on Signal Layer 4 "VDD_CORE_L05_P104" (solid, remove dead copper, pour order 104): 47.975,65.003 44.397,61.425 42.4,61.425 41.75,60.775 41.75,59.5 28.2,59.5 28.2,60.45 29.65,60.45 30.425,61.225 31,61.225 31.375,61.6 31.375,63.4 31.55,63.575 32.2,63.575 32.475,63.85 32.475,77.225 33.225,77.975 36.425,77.975 39.75,81.3 42.775,81.3 44.475,81.3 45.125,81.95 45.125,84.1 45.475,84.45 47.5,84.45 47.975,83.975
VDD_DDR on Signal Layer 4 "VDD_DDR" (solid, pour order 72): 42.845,58.92 48.5,64.575 48.5,84 49.15,84.65 51.25,84.65 52.525,83.375 52.525,55.325 47.55,50.35 47.55,35.45 47.55,3.15 18.25,3.15 18.25,58.92
NetC7_2 on Signal Layer 4 "NETC7_2_L05_P168" (solid, remove dead copper, pour order 168): 34.575,91.025 34.575,90.075 34.575,86.9 34.9,86.575 35.125,86.35 36.925,86.35 37.325,86.75 37.325,89.2 36.574,89.951 36.576,104.276 38.375,106.075 54.05,106.075 54.5,106.525 54.5,107.8 54.025,108.275 37.425,108.275 34.575,105.425
VIN on Signal Layer 4 "VIN_L05_P276" (solid, remove dead copper, pour order 276): 37.075,102.875 36.775,102.575 36.775,100.25 37.775,99.25 37.775,96.625 37.95,96.45 38.4,96.45 39.125,97.175 39.125,102.625 38.875,102.875
NetC6_2 on Signal Layer 4 "NETC6_2_L05_P024" (solid, remove dead copper, pour order 24): 38.85,103.15 37.05,103.15 36.775,103.425 36.775,104.05 37.7,104.975 38.35,105.625 44.9,105.625 45.6,104.925 45.6,94.925 45.6,86.25 45.15,85.8 43.4,85.8 42.975,86.225 42.975,90.55 41.425,92.1 41.45,92.125 41.45,94.85 39.25,97.05 39.25,102.75
VDD on Signal Layer 4 "VDD_L05_P258" (solid, remove dead copper, pour order 258): 63.525,60.775 62.9,60.15 61.825,59.075 58.7,59.075 57.525,60.25 57.525,62.45 57.25,62.725 55.6,62.725 55.25,62.375 55.25,55.175 56.225,54.2 63.925,54.2 65.075,55.35 65.075,60.5 64.8,60.775
GND on Signal Layer 4 "GND_L05_P280" (solid, remove dead copper, pour order 280): 48.25,105.625 53.225,105.625 53.85,105 53.85,103.2 54.275,102.775 56.65,102.775 58.2,101.225 58.2,89.075 53.95,84.825 46.275,84.825 45.85,85.25 45.85,105.15 46.325,105.625
GND on Signal Layer 3 "GND_L04_P274" (solid, remove dead copper, pour order 274): 0,120 0,0 86,0 86,120
VIN on Signal Layer 3 "VIN_L04_P254" (solid, remove dead copper, pour order 254): 46.55,114.875 37.725,114.875 35.5,112.65 35.5,96.475 36.45,95.525 45.225,95.525 46.925,93.825 46.925,86.65 48.225,85.35 56.475,85.35 64.35,93.225 68.575,93.225 70.15,91.65 70.15,79.925 71.575,78.5 75.65,78.5 80.725,83.575 80.725,106.15 77.95,108.925 70.525,108.925 64.593,114.857 51.475,114.857
NetBT1_1 on Signal Layer 3 "NETBT1_1_L04_P082" (solid, remove dead copper, pour order 82): 11.75,101.225 11.4,100.875 11.4,98.375 11.7,98.075 15.75,98.075 21.425,103.75 24.575,103.75 24.925,104.1 24.925,106.175 24.575,106.525 19.35,106.525 16.1,103.275 16.1,102.1 15.225,101.225
GND on Signal Layer 1 "GND" (solid, pour order 100): 86,0 0,0 0,120 86,120

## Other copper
Top Layer:
  pour cut-out: 46.325,98.35 51.425,98.35 51.425,94.225 46.325,94.225
  pour cut-out: 62.65,15.55 62.225,15.125 62.225,14.7 61.975,14.45 61,14.45 60.275,13.725 60.275,12.65 59.75,12.125 57.175,12.125 56.845,11.795 56.845,3.32 56.475,2.95 56.6,2.825 56.6,2.775 56.875,2.5 66.375,2.5 68.125,4.25 68.125,11.275 67.25,12.15 65.485,12.15 65.175,12.46 65.175,15.125 64.675,15.625 62.75,15.625
  pour cut-out: 3.175,67.206 2.981,67.206 2.8,67.025 2.8,65.942 4.5,64.242 4.5,62.35 4.65,62.2 9.9,62.2 11.5,63.8 11.5,67.2
  pour cut-out: 53.4,66.825 53.4,66.1 56.275,63.225 61.727,63.225 62.377,63.875 62.35,63.902 62.35,66.825
  pour cut-out: 77.213,84.05 77.4,83.863 77.4,81.175 78.325,80.25 83.575,80.25 83.975,79.85 83.975,78.6 82.6,77.225 71.525,77.225 70.491,78.259 70.491,79.916 73.925,83.35 76.025,83.35 76.725,84.05
  pour cut-out: 11.7,73.675 11.7,67.175 12.51,66.365 22.625,66.365 22.625,66.8 15.75,73.675
  pour cut-out: 65.125,80.75 64.225,79.85 64.225,77.375 64.975,76.625 71.15,76.625 71.675,77.15 71.675,80.2 71.125,80.75
  text "1" at 6.25,3 h1.5
  text ".Layer_Name" at 7.068,-11.667 h3
  text ".GTL" at 48.763,-11.667 h3
Signal Layer 1:
  text "2" at 7.5,3 h1.5
  text ".Layer_Name" at 7.068,-11.667 h3
  text ".G1" at 48.763,-11.667 h3
Signal Layer 2:
  pour cut-out: 10.45,65.425 10.35,65.325 10.35,63.075 11.05,62.375 21.875,62.375 22.85,63.35 22.85,65.425
  pour cut-out: 39.175,71.725 38.726,71.725 37.05,70.049 37.05,63.45 36.25,62.65 36.25,62.137 36.712,61.675 40.525,61.675 41.2,62.35 51.6,62.35 54.8,59.15 56.775,59.15 57.6,59.975 57.595,59.98 57.595,62.92 57.85,63.175 59.75,63.175 60.325,62.6 60.325,61.3 60.95,60.675 76.775,60.675 77.75,61.65 79.075,61.65 80.45,63.025 80.45,71.275 79.775,71.95 39.4,71.95 39.2,71.75
  text "3" at 8.75,3 h1.5
  text ".Layer_Name" at 7.068,-11.667 h3
  text ".G2" at 48.763,-11.667 h3
Signal Layer 3:
  pour cut-out: 80.166,79.516 80.158,79.525 77.35,79.525 76.2,78.375 76.2,76.55 75.575,75.925 73.95,75.925 72.25,74.225 72.25,69.415 71.775,68.94 71.775,68.05 73.8,66.025 73.8,62.525 74.675,61.65 74.675,57.075 74.1,56.5 74.1,56.075 73.275,55.25 72.6,55.25 72.5,55.15 72.5,55 73.05,54.45 73.07,54.45 73.62,53.9 75.925,53.9 77.05,52.775 78.95,52.775 79.287,53.112 79.287,59.012 79.525,59.25 80.471,59.25 80.675,59.046 80.675,57.825 80.85,57.65 81.7,57.65 82.075,57.275 83.875,59.075 83.875,64.4 81.55,66.725 80.1,66.725 79.8,66.425 79.8,65.375 79.425,65 77.95,65 77.35,65.6 77.35,66.925 80.725,70.3 80.725,79.3 80.5,79.525
  text "4" at 10,3 h1.5
  text ".Layer_Name" at 7.1,-11.65 h3
  text ".G3" at 48.795,-11.65 h3
Signal Layer 4:
  text "5" at 11.25,3 h1.5
  text ".Layer_Name" at 7.1,-11.65 h3
  text ".G4" at 48.795,-11.65 h3
Bottom Layer:
  pour cut-out: 67.45,12.4 67.45,4.375 67.65,4.175 69.775,4.175 70.175,4.575 70.175,12.225 70,12.4
  text "6" at 12.5,3 h1.5
  text ".GBL" at 37.56,-11.699 h3
  text ".Layer_Name" at 78.874,-11.699 h3
Multi-Layer:
  pour cut-out: 6.125,4.375 6.125,2.625 13.75,2.625 13.75,4.375

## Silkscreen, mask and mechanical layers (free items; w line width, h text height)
Top Overlay:
  lines w0.12: 34.8,77.425 33.725,77.425 ; 34.85,74.7 34.85,79.775 ; 33.725,77.425 33.925,77.625 33.925,77.225 33.725,77.425 ; 1.5,94.325 1.5,102.075 9.5,102.075 9.5,94.325 1.5,94.325 ; 64.275,20.125 74.275,20.125 74.275,47.125 64.275,47.125 64.275,20.125 ; 78.25,19.75 78.25,47.25 82.75,47.25 82.75,19.75 78.25,19.75
  text "Reset" at 3.9,114.85 h2
  text "User PA13" at 11.225,114.8 h2
  text "User PA14" at 21.4,114.8 h2
  text "Wake up" at 32.925,114.8 h2
  text "5V-3A" at 63.8,114.775 h3
  text "ST-Link V2-1" at 69.625,97.725 h2
  text "Boot 2" at 5,95.1 h2.5 r90
  text "Boot 1" at 7,95.1 h2.5 r90
  text "- - - - -" at 3,95.075 h2.5 r90
  text "Boot 0" at 9,95.075 h2.5 r90
  text "3V3" at 79.525,90.975 h1.5
  text "CLK" at 79.4,88.3 h1.5
  text "GND" at 79.108,85.715 h1.5
  text "DIO" at 79.722,83.274 h1.5
  text "C" at 66.477,77.169 h15
  text "G" at 67.402,68.444 h12
  text "H" at 66.877,60.444 h15
  text "I" at 68.527,50.494 h15
  text "STM32MP15X-EVAL" at 81.5,21 h3 r90
  text "µSD" at 77.625,11.725 h3
  text "J" at 5.325,10.925 h15
  text "MB1263C" at 4,7 h3
  text "E" at 75.275,3.2 h15
  text ".Layer_Name" at 7.068,-11.667 h3
  text ".GTO" at 48.763,-11.667 h3
Bottom Overlay:
  lines w0.12: 16.35,20.5 16.35,5.725 16.4,5.675 ; 16.4,15.15 20.35,15.15 20.087,14.887 20.087,15.413 20.338,15.162 ; 23.775,3.4 24.325,3.4 25.225,4.3 ; 36.825,6.575 36.825,7.1 36.875,7.15 43.925,7.15 ; 37.6,63.25 36.75,63.25 ; 36.75,63.25 37,63.5 37,63 36.75,63.25 ; 37.2,60.975 37.2,67.3 40.325,70.425 44,70.425 44.575,71 50.775,71 51.35,70.425 54.5,70.425 54.5,60.975 37.2,60.975
  text "3V3" at 35.4,80.475 h2 r270
  text "VDD" at 43.525,79.475 h2 r270
  text "VDD_DDR" at 50.375,74.6 h2 r270
  text "VDD_CORE" at 45.35,73.1 h2 r270
  text "µSD" at 80.375,19.575 h3
  text ".GBO" at 37.56,-11.699 h3
  text ".Layer_Name" at 78.874,-11.699 h3
Top Paste:
  text ".Layer_Name" at 7.068,-11.667 h3
  text ".GTP" at 48.763,-11.667 h3
Bottom Paste:
  text ".GBP" at 37.56,-11.699 h3
  text ".Layer_Name" at 78.874,-11.699 h3
Top Solder:
  region: 6.125,4.375 6.125,2.625 13.75,2.625 13.75,4.375
  text ".Layer_Name" at 7.068,-11.667 h3
  text ".GTS" at 48.763,-11.667 h3
Bottom Solder:
  region: 6.125,4.375 6.125,2.625 13.75,2.625 13.75,4.375
  text ".GBS" at 37.56,-11.699 h3
  text ".Layer_Name" at 78.874,-11.699 h3
M1-Board Shape:
  lines w0.01: 85.5,120 85.5,120
  lines w0.1: 0,0.5 ccw(c0.5,0.5) 0.5,0 85.5,0 ccw(c85.5,0.5) 86,0.5 86,119.5 ccw(c85.5,119.5) 85.5,120 0.5,120 ccw(c0.5,119.5) 0,119.5 0,0.5
M2-Board Dimensions:
  text ".Layer_Name" at 7.068,-11.667 h3
  text ".GM2" at 48.763,-11.667 h3
M8-Bottom Info:
  lines w0.1: 38.58,59.425 38.58,70.525 47.68,70.525 47.68,59.425 38.58,59.425
  text "ZONE / COMPONENT U11 / PROJECT MB1262A / H : 1mm" at 47.4,63.65 h1
M14-Top Assembly:
  text ".Layer_Name" at 7.068,-11.667 h3
  text ".GM14" at 48.763,-11.667 h3
M15-Bottom Assembly:
  text ".GM15" at 37.56,-11.699 h3
  text ".Layer_Name" at 78.874,-11.699 h3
